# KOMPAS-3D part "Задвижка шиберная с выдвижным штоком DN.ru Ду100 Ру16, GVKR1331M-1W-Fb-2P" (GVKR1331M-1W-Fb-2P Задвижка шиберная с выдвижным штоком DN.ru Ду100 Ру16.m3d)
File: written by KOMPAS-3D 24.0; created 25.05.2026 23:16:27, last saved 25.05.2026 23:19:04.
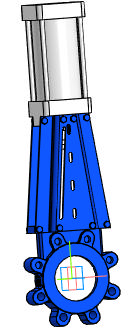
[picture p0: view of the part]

Document properties: Автор: R2D2; Полное имя файла: E:\Работа\Зайцев\GVKR1331M-1W-Fb-2P Задвижка шиберная с выдвижным штоком DN.ru Ду50-300 Ру16-10-6 с пневмоприводом\исходные материалы\DN100\DN100\GVKR1331M-1W-Fb-2P Задвижка шиберная с выдвижным штоком DN.ru Ду100 Ру16.m3d

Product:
- Part/product: Задвижка шиберная с выдвижным штоком DN.ru Ду100 Ру16  | designation GVKR1331M-1W-Fb-2P
    Масса: 12.5
    Раздел спецификации: Прочие изделия
    Примечание: D040-08794

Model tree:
1. Операция без истории:1

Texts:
  GVKR1331M-1W-Fb-2P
